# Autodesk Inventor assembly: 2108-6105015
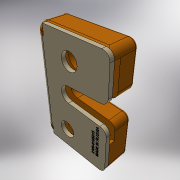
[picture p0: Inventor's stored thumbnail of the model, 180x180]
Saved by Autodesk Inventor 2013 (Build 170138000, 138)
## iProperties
Shininess: 64.0
Length Units: 11269
Angle Units: 11279
Time Units: 11290
Mass Units: 11283
Length Display Precision: 3
Angle Display Precision: 2
Compacted: True
Created: 2005-02
Part Number: 2108-6105015
Document SubType Name: Assembly
Designer: =<Author>
Manufacturer: Standard
Standards Organization: Custom
Description: =<Part Number>
Mass: 75.2962 g
Surface Area: 228.896 cm^2
Volume: 51.7943 cm^3
Density: 1.45376 g/cm^3
Density: 0.0
Volumn: 0.0
Area: 0.0
PropertySet Name: Model Information
Control State: 0
Master: False
Checked Out: False
Checked Out Date: 2008-10-15
Last Check In Date: 2008-10-15
Author: PVitaliy
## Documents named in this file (4)
- Y:\Dropbox\Launch 2013\Eco Material Advisor\Assy, Door\_Data\Assy, Cab\2108-6105015.iam
- Y:\Dropbox\Launch 2013\Eco Material Advisor\Assy, Door\_Data\Assy, Cab\Housing 1.ipt
- Y:\Dropbox\Launch 2013\Eco Material Advisor\Assy, Door\_Data\Assy, Cab\Housing 2.ipt
- Y:\Dropbox\Launch 2013\Eco Material Advisor\Assy, Door\_Data\Assy, Cab\axis.ipt
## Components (3 placed, 3 different names)
1. Housing 1:1 — Flush:1, Flush:2, Flush:3
2. Housing 2:1 — Flush:1, Flush:2, Flush:3, Insert:3
3. axis:1 — Insert:3
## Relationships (4: Flush 3, Insert 1)
- Flush:1: Housing 1:1 ↔ Housing 2:1
- Flush:2: Housing 1:1 ↔ Housing 2:1
- Flush:3: Housing 1:1 ↔ Housing 2:1
- Insert:3: Housing 2:1 ↔ axis:1
